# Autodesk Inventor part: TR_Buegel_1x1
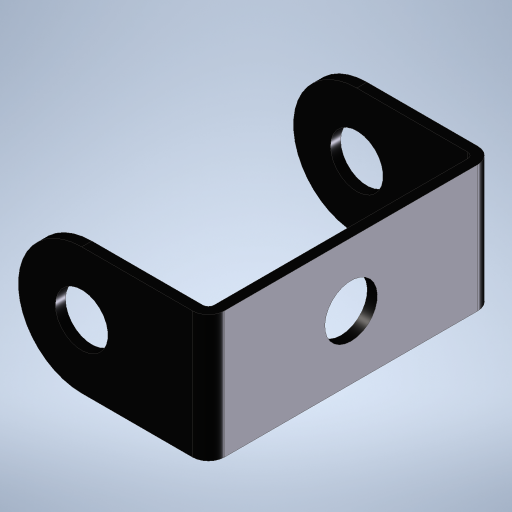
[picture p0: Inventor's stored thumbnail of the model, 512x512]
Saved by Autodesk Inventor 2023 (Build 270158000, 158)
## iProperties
Created: 2023-11
Part Number: TR_Buegel_1x1
Material: Edelstahl
Document SubType Name: Modeling
Designer: Admin
Density: 8 g/cm^3
Appearance: Halbpoliert
Author: Admin
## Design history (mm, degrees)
sketch "Skizze1"
  geometry: L1 (15, 11.25)-(1.25, 11.25); L2 (0, 10)-(0, -10); L3 (1.25, -11.25)-(15, -11.25); L4 (15, -11.25)-(15, -10.45); L5 (15, -10.45)-(1.25, -10.45); L6 (0.8, -10)-(0.8, 10); L7 (1.25, 10.45)-(15, 10.45); L8 (15, 10.45)-(15, 11.25); A1 r 1.25 centre (1.25, 10) between (1.25, 11.25) and (0, 10); A2 r 1.25 centre (1.25, -10) between (0, -10) and (1.25, -11.25); A3 r 0.45 centre (1.25, 10) between (1.25, 10.45) and (0.8, 10); A4 r 0.45 centre (1.25, -10) between (0.8, -10) and (1.25, -10.45); 5 further points
  constraints: 16 end point, 8 point on circle, 8 tangent, 4 centre point, 4 point on line, 3 horizontal, 3 perpendicular, 2 equal radius, 2 midpoint, 2 vertical alignment, 1 coincident, 1 collinear, 1 horizontal alignment, 1 parallel, 1 vertical
  dimensions: "d0" = 0.8 distance of L7.end L1.start (= Dicke); "d1" = 15 horizontal distance of point (0, 0) L1.start; "d2" = 0.8 horizontal distance of point (0, 0) point (0.8, 10.45) (= Dicke); "d6" = 1.25 radius of A1; "d7" = 22.5 distance of L3.end L1.start
extrude "Extrusion1" new body sketch "Skizze1" stored distance "d8" = 10 (= Einheitsmaß); taper "d9" = 0 deg
fillet "Rundung1" dims "d10" = 5 (= 0.5 x Einheitsmaß)
sketch "Skizze2"
  geometry: C1 r 2.075 at (-10, 0); A1 r 5 centre (-10, 0) between (-10, 5) and (-10, -5) reference; 1 further point
  constraints: 1 centre point, 1 coincident
  dimensions: "d11" = 4.15 diameter of C1 (= 2 x Radius)
extrude "Extrusion2" cut sketch "Skizze2" extent not by distance; stored distance "d12" = 0; taper "d13" = 0 deg
sketch "Skizze3"
  geometry: C1 r 2.075 at (0, 0); 1 further point
  constraints: 1 centre point, 1 coincident
  dimensions: "d14" = 4.15 diameter of C1 (= 2 x Radius)
extrude "Extrusion3" cut sketch "Skizze3" extent not by distance; stored distance "d15" = 0; taper "d16" = 0 deg
node "Volumenkörper1"
other parameters: "Einheitsmaß" = 10 [user parameter; used in 2 equation terms], "Radius" = 2.075 [user parameter; used in 2 equation terms], "Fasen" = 0.5 [user parameter], "Dicke" = 0.8 [user parameter; used in 2 equation terms]
